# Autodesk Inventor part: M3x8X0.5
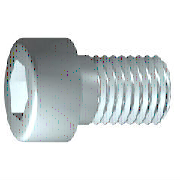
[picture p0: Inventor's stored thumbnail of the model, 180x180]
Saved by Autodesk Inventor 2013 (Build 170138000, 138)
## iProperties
IsCustomPart: 1
Created: 2009-02
Part Number: M3x8X0.5
Material: 강, 연강
Description: 6각머리 태핑 나사
Document SubType Name: Modeling
Standard: KS B 1003
Designer: SeoGD™[esajin.kr]
Standards Organization: KS
Language: ko-KR
Size Designation: M 3 x 8
Categories: <MemberInstance><Categories><Category DisplayName="조임쇠" InternalName="e4da775c-781d-43d5-af7c-5136215cf5a6" Mnemonic="FSTN"><Category DisplayName="볼트" InternalN
Density: 1 g/cm^3
Author: SeoGD™[esajin.kr]
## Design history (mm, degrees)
sketch "스케치1"
  geometry: L1 (-0.867, 0)-(8, 0); L2 (8, 0)-(8, 1.5); L3 (8, 1.5)-(1.25, 1.5); L4 (1.25, 1.5)-(0.943, 1.5); L5 (0.943, 1.5)-(0, 1.5); L6 (0, 1.5)-(0, 2.75); L7 (0, 2.75)-(-3, 2.75); L8 (-3, 2.75)-(-3, 1.443); L9 (-3, 1.443)-(-1.7, 1.443); L10 (-1.7, 1.443)-(-0.867, 0); L11 (-5.2, 0)-(10.2, 0) reference; L12 (0, -0.55)-(0, 3.3) reference; L13 (1.25, 1.5)-(0, 1.5)
  constraints: 22 end point, 6 parallel, 2 collinear, 2 perpendicular, 1 horizontal, 1 point on line
  dimensions: "d1" = 6.75 distance from line of L3.end L2 (= GEL); "d2" = 0.30683 distance of L4.end L3.end (computed from GAL); "d3" = 3 distance between parallel lines of L8 L6 (= KOH); "d4" = 1.3 distance of L8.end L9.end (= INTI); "d5" = 60 deg angle of L10 L1; "d6" = 3 diameter of L3 L1 (= GD); "d7" = 3 diameter of L5 L1 (= BDM); "d8" = 2.88675 diameter of L9 L1 (= 1.1547 x SW); "d9" = 5.5 diameter of L7 L1 (= KOD); "d26" = 8 distance between parallel lines of L12 L2 (= NLG)
revolve "본체" sketch "스케치1" stored, may be unused: angle "d10" = 90 deg
sketch "스케치2"
  geometry: L1 (0, -3.85)-(0, 3.85) reference; L2 (-3.85, 0)-(3.85, 0) reference; L3 (1.443, 0)-(0.722, -1.25); L4 (0.722, -1.25)-(-0.722, -1.25); L5 (-0.722, -1.25)-(-1.443, 0); L6 (-1.443, 0)-(-0.722, 1.25); L7 (-0.722, 1.25)-(0.722, 1.25); L8 (0.722, 1.25)-(1.443, 0); 2 further points
  constraints: 12 end point, 1 coincident, 1 horizontal alignment, 1 point on line, 12 other
extrude "슬롯" join sketch "스케치2" stored distance "d11" = 10; taper "d12" = 0 deg
workplane "Work Plane1"
fillet "Fillet2" dims "d30" = 0.1 (= R)
body "Solid1"
fillet "모깎기1" dims "d17" = 0.3 (= RR)
feature "스레드" dims "d13" = 6.75 (= GEL), "d14" = 0
chamfer "모따기1" distance "d15" = 0.30673 (= -0.5 x SPD + 0.5 x GD); stored, may be unused: second distance "d16" = 0.30673 (= GUL), angle "d27" = 45 deg
other parameters: "GD" = 3 (= NND) [user parameter; used in 2 equation terms], "NLG" = 8 [user parameter; used in 1 equation term], "GEL" = 6.75 [user parameter; used in 2 equation terms], "KOD" = 5.5 [user parameter; used in 1 equation term], "KOH" = 3 [user parameter; used in 1 equation term], "INTI" = 1.3 [user parameter; used in 1 equation term], "GAL" = 0.30673 (= 0.61345 x PTC) [user parameter; used in 1 equation term], "GUL" = 0.30673 (= 0.61345 x PTC) [user parameter; used in 1 equation term], "BDM" = 3 (= NND) [user parameter; used in 1 equation term], "SW" = 2.5 [user parameter; used in 2 equation terms], "RR" = 0.3 [user parameter; used in 1 equation term], "SPD" = 2.38655 (= NND - 1.2269 x PTC) [user parameter; used in 1 equation term], "d19" = 0, "d28" = 0, "d29" = 0, "R" = 0.1 [user parameter; used in 1 equation term], "PHH" = 0.1 [user parameter], "GD1" = 2.38655 (= THREADDIA - 1.2269 x PTC) [user parameter], "THREADDIA" = 3 [user parameter; used in 1 equation term], "FAWI" = 45 deg [user parameter], "PTC" = 0.5 [user parameter; used in 5 equation terms], "NND" = 3 [user parameter; used in 3 equation terms], "TOA" = 30 deg [user parameter], "E0" = 2.8875 (= 1.155 x SW) [user parameter]
